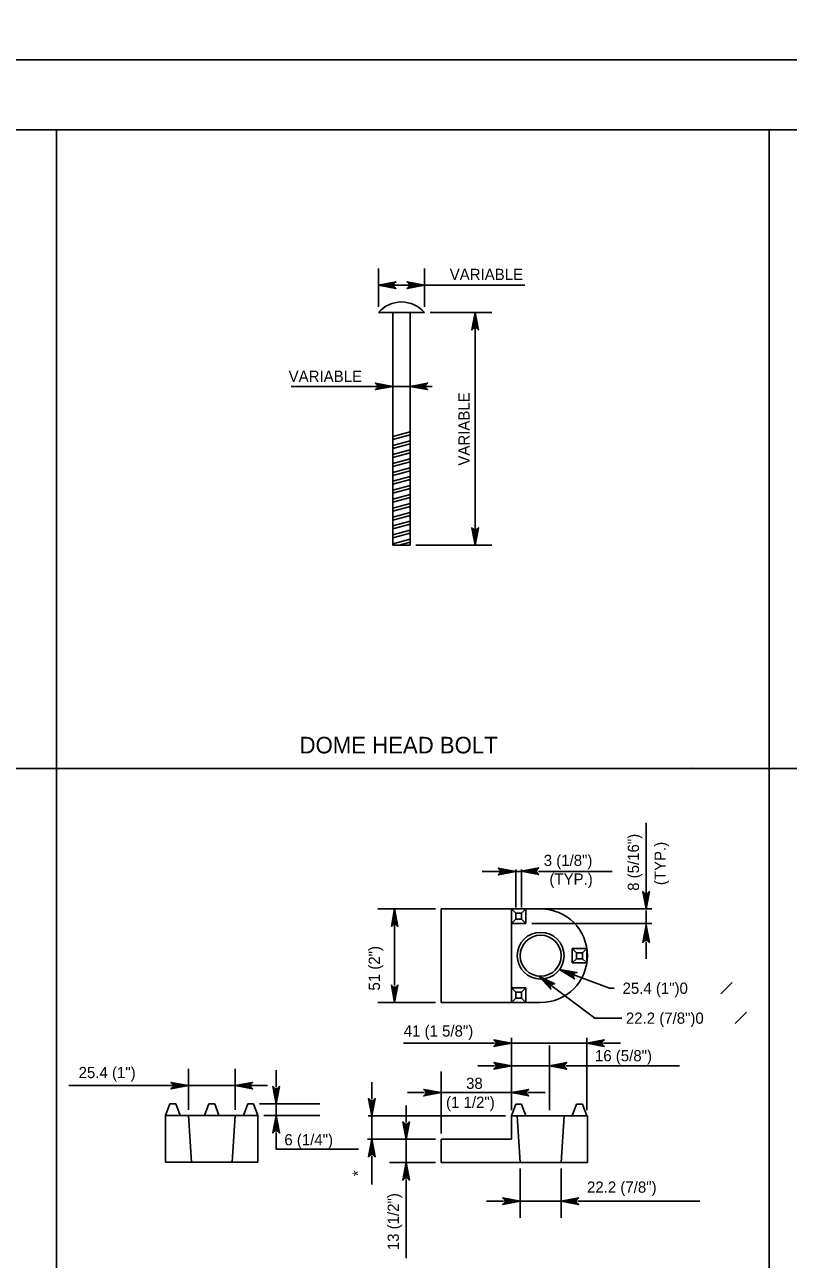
# Model space of a CAD drawing. Extents: x 0 to 36.3, y -66 to 0.
# Drawn here: x 9.04 to 17.21, y -56.84 to -43.62 of the extents above; entities that cross this region are included whole.
import ezdxf

# ---------------------------------------------------------------- set-up
doc = ezdxf.new("R2010")
doc.units = 0
for name, color, linetype in [('1', 7, 'Continuous'), ('3', 7, 'Continuous'), ('4', 7, 'Continuous'), ('5', 7, 'Continuous'), ('63', 7, 'Continuous')]:
    doc.layers.add(name, color=color, linetype=linetype)

msp = doc.modelspace()

# ---------------------------------------------------------------- linework, layer by layer
at = {"layer": '1'}
msp.add_lwpolyline([(1.75, -65.25), (33.25, -65.25), (33.25, -44.75), (1.75, -44.75)], close=True, dxfattribs=at)
at = {"layer": '3'}
for p, q in [((9.375, -65.25), (9.375, -44.75)), ((17, -65.25), (17, -44.75)), ((12.821, -46.643), (12.821, -46.234)), ((13.313, -46.643), (13.313, -46.234)), ((12.821, -46.412), (14.388, -46.412)), ((13.313, -46.412), (13.313, -46.412)), ((13.375, -46.705), (14.033, -46.705)), ((13.855, -49.193), (13.855, -46.705)), ((12.857, -47.495), (11.887, -47.495)), ((12.975, -47.451), (12.975, -47.672)), ((13.16, -47.495), (12.975, -47.495)), ((13.16, -47.451), (13.16, -47.672)), ((13.278, -47.495), (13.396, -47.495)), ((13.221, -49.193), (14.033, -49.193)), ((1.75, -51.583), (32.25, -51.583)), ((16.171, -51.569), (16.171, -51.569)), ((16.482, -53.994), (16.604, -53.872)), ((16.638, -54.312), (16.76, -54.19))]:
    msp.add_line(p, q, dxfattribs=at)
for points in [[(12.821, -46.412), (13.008, -46.377), (12.993, -46.387), (12.986, -46.399), (12.984, -46.412), (12.986, -46.424), (12.993, -46.437), (13.008, -46.447), (12.821, -46.412), (12.993, -46.437), (12.986, -46.424), (12.821, -46.412), (12.984, -46.412), (12.986, -46.399), (12.821, -46.412), (12.993, -46.387)], [(13.313, -46.412), (13.127, -46.447), (13.141, -46.437), (13.149, -46.424), (13.151, -46.412), (13.149, -46.399), (13.141, -46.387), (13.127, -46.377), (13.313, -46.412), (13.141, -46.387), (13.149, -46.399), (13.313, -46.412), (13.151, -46.412), (13.149, -46.424), (13.313, -46.412), (13.141, -46.437)], [(13.855, -46.705), (13.89, -46.891), (13.88, -46.877), (13.868, -46.869), (13.855, -46.867), (13.843, -46.869), (13.83, -46.877), (13.821, -46.891), (13.855, -46.705), (13.83, -46.877), (13.843, -46.869), (13.855, -46.705), (13.855, -46.867), (13.868, -46.869), (13.855, -46.705), (13.88, -46.877)], [(12.975, -47.495), (12.789, -47.53), (12.803, -47.52), (12.81, -47.508), (12.812, -47.495), (12.81, -47.483), (12.803, -47.47), (12.789, -47.46), (12.975, -47.495), (12.803, -47.47), (12.81, -47.483), (12.975, -47.495), (12.812, -47.495), (12.81, -47.508), (12.975, -47.495), (12.803, -47.52)], [(13.16, -47.495), (13.346, -47.46), (13.332, -47.47), (13.324, -47.483), (13.322, -47.495), (13.324, -47.508), (13.332, -47.52), (13.346, -47.53), (13.16, -47.495), (13.332, -47.52), (13.324, -47.508), (13.16, -47.495), (13.322, -47.495), (13.324, -47.483), (13.16, -47.495), (13.332, -47.47)], [(13.855, -49.193), (13.821, -49.007), (13.83, -49.021), (13.843, -49.028), (13.855, -49.03), (13.868, -49.028), (13.88, -49.021), (13.89, -49.007), (13.855, -49.193), (13.88, -49.021), (13.868, -49.028), (13.855, -49.193), (13.855, -49.03), (13.843, -49.028), (13.855, -49.193), (13.83, -49.021)]]:
    msp.add_lwpolyline(points, dxfattribs=at)
for points in [[(12.939, -46.431), (12.939, -46.392), (12.821, -46.412)], [(13.195, -46.431), (13.195, -46.392), (13.313, -46.412)], [(13.875, -46.823), (13.836, -46.823), (13.855, -46.705)], [(12.857, -47.475), (12.857, -47.515), (12.975, -47.495)], [(13.278, -47.475), (13.278, -47.515), (13.16, -47.495)], [(13.875, -49.075), (13.836, -49.075), (13.855, -49.193)]]:
    msp.add_lwpolyline(points, close=True, dxfattribs=at)
at = {"layer": '4'}
for p, q in [((12.821, -46.705), (12.821, -46.705)), ((12.821, -46.705), (13.313, -46.705)), ((12.975, -46.705), (12.975, -47.972)), ((13.16, -46.705), (13.16, -47.972)), ((13.313, -46.705), (13.313, -46.705)), ((12.975, -47.972), (12.975, -49.193)), ((13.16, -47.972), (13.16, -49.193)), ((12.975, -49.193), (13.16, -49.193)), ((13.16, -49.193), (13.16, -49.193)), ((15.684, -52.923), (15.684, -52.165)), ((14.352, -52.687), (13.929, -52.687)), ((14.289, -53.071), (14.289, -52.663)), ((14.352, -53.071), (14.352, -52.663)), ((14.532, -52.687), (15.32, -52.687)), ((13.43, -53.087), (12.814, -53.087)), ((12.994, -53.907), (12.994, -53.087)), ((13.493, -53.087), (13.493, -54.087)), ((13.493, -53.087), (14.556, -53.087)), ((14.243, -53.087), (14.243, -54.087)), ((14.243, -53.087), (14.289, -53.133)), ((14.398, -53.087), (14.352, -53.133)), ((14.398, -53.087), (14.398, -53.243)), ((14.461, -53.087), (15.746, -53.087)), ((15.684, -53.259), (15.684, -53.103)), ((14.289, -53.197), (14.243, -53.243)), ((14.289, -53.133), (14.289, -53.197)), ((14.289, -53.133), (14.352, -53.133)), ((14.289, -53.197), (14.352, -53.197)), ((14.352, -53.133), (14.352, -53.197)), ((14.352, -53.197), (14.398, -53.243)), ((14.243, -53.243), (14.398, -53.243)), ((14.461, -53.243), (15.746, -53.243)), ((15.684, -53.439), (15.684, -53.619)), ((14.894, -53.509), (14.941, -53.556)), ((15.05, -53.509), (14.894, -53.509)), ((14.894, -53.509), (14.894, -53.665)), ((14.941, -53.619), (14.894, -53.665)), ((14.941, -53.556), (14.941, -53.619)), ((14.941, -53.556), (15.004, -53.556)), ((14.941, -53.619), (15.004, -53.619)), ((15.05, -53.509), (15.004, -53.556)), ((15.004, -53.556), (15.004, -53.619)), ((15.004, -53.619), (15.05, -53.665)), ((15.05, -53.509), (15.05, -53.665)), ((14.894, -53.665), (15.05, -53.665)), ((14.398, -53.932), (14.243, -53.932)), ((14.243, -53.932), (14.289, -53.978)), ((14.289, -53.978), (14.289, -54.041)), ((14.289, -53.978), (14.352, -53.978)), ((14.398, -53.932), (14.352, -53.978)), ((14.352, -53.978), (14.352, -54.041)), ((14.398, -53.932), (14.398, -54.087)), ((13.43, -54.087), (12.814, -54.087)), ((13.493, -54.087), (14.556, -54.087)), ((14.289, -54.041), (14.243, -54.087)), ((14.243, -54.087), (14.398, -54.087)), ((14.289, -54.041), (14.352, -54.041)), ((14.352, -54.041), (14.398, -54.087)), ((15.135, -54.255), (15.424, -54.255)), ((14.063, -54.523), (13.089, -54.523)), ((14.243, -55.239), (14.243, -54.465)), ((14.243, -54.523), (15.05, -54.523)), ((14.243, -55.239), (14.243, -54.549)), ((14.649, -55.239), (14.649, -54.549)), ((15.05, -55.239), (15.05, -54.465)), ((15.23, -54.523), (15.41, -54.523)), ((10.787, -55.235), (10.787, -54.797)), ((11.287, -55.235), (11.287, -54.797)), ((11.727, -54.991), (11.727, -54.811)), ((14.063, -54.766), (13.883, -54.766)), ((14.243, -54.766), (14.649, -54.766)), ((14.243, -55.239), (14.243, -54.784)), ((14.829, -54.766), (16.041, -54.766)), ((12.751, -55.121), (12.751, -54.941)), ((13.493, -55.489), (13.493, -54.825)), ((9.508, -54.977), (10.622, -54.977)), ((10.787, -54.977), (11.287, -54.977)), ((11.633, -54.977), (11.453, -54.977)), ((13.313, -55.052), (13.133, -55.052)), ((13.493, -55.052), (14.243, -55.052)), ((14.423, -55.052), (14.603, -55.052)), ((10.59, -55.171), (10.543, -55.297)), ((10.653, -55.171), (10.59, -55.171)), ((10.653, -55.171), (10.699, -55.297)), ((11.006, -55.171), (10.961, -55.297)), ((11.069, -55.171), (11.006, -55.171)), ((11.069, -55.171), (11.114, -55.297)), ((11.422, -55.171), (11.376, -55.297)), ((11.485, -55.171), (11.422, -55.171)), ((11.485, -55.171), (11.531, -55.297)), ((11.548, -55.171), (12.194, -55.171)), ((11.727, -55.171), (11.727, -55.297)), ((13.118, -55.371), (13.118, -55.191)), ((14.243, -55.301), (14.289, -55.176)), ((14.289, -55.176), (14.352, -55.176)), ((14.352, -55.176), (14.398, -55.301)), ((14.894, -55.301), (14.941, -55.176)), ((14.941, -55.176), (15.004, -55.176)), ((15.004, -55.176), (15.05, -55.301)), ((11.531, -55.297), (10.543, -55.297)), ((10.543, -55.297), (10.543, -55.797)), ((10.787, -55.297), (10.819, -55.797)), ((11.287, -55.297), (11.256, -55.797)), ((11.531, -55.297), (11.531, -55.797)), ((11.594, -55.297), (12.194, -55.297)), ((14.18, -55.301), (12.712, -55.301)), ((12.751, -55.301), (12.751, -55.551)), ((14.243, -55.301), (15.056, -55.301)), ((14.243, -55.301), (14.243, -55.551)), ((14.337, -55.801), (14.306, -55.301)), ((14.774, -55.801), (14.806, -55.301)), ((15.056, -55.301), (15.056, -55.801)), ((11.727, -55.477), (11.727, -55.657)), ((13.43, -55.551), (12.703, -55.551)), ((13.43, -55.551), (12.938, -55.551)), ((13.118, -55.551), (13.118, -55.801)), ((13.493, -55.551), (14.243, -55.551)), ((13.493, -55.551), (13.493, -55.801)), ((11.727, -55.657), (12.608, -55.657)), ((12.751, -55.731), (12.751, -56.035)), ((11.531, -55.797), (10.543, -55.797)), ((13.43, -55.801), (12.938, -55.801)), ((13.43, -55.801), (13.25, -55.801)), ((13.493, -55.801), (15.056, -55.801)), ((14.337, -55.864), (14.337, -56.393)), ((14.774, -55.864), (14.774, -56.393)), ((13.118, -55.981), (13.118, -56.825)), ((14.157, -56.213), (13.977, -56.213)), ((14.337, -56.213), (14.774, -56.213)), ((14.954, -56.213), (16.259, -56.213))]:
    msp.add_line(p, q, dxfattribs=at)
for points in [[(14.289, -52.687), (14.102, -52.722), (14.117, -52.712), (14.124, -52.7), (14.126, -52.687), (14.124, -52.675), (14.117, -52.662), (14.102, -52.652), (14.289, -52.687), (14.117, -52.662), (14.124, -52.675), (14.289, -52.687), (14.126, -52.687), (14.124, -52.7), (14.289, -52.687), (14.117, -52.712)], [(14.349, -52.683), (14.536, -52.648), (14.521, -52.658), (14.514, -52.67), (14.512, -52.683), (14.514, -52.695), (14.521, -52.708), (14.536, -52.718), (14.349, -52.683), (14.521, -52.708), (14.514, -52.695), (14.349, -52.683), (14.512, -52.683), (14.514, -52.67), (14.349, -52.683), (14.521, -52.658)], [(15.684, -53.087), (15.649, -52.901), (15.659, -52.915), (15.672, -52.923), (15.684, -52.925), (15.697, -52.923), (15.709, -52.915), (15.719, -52.901), (15.684, -53.087), (15.709, -52.915), (15.697, -52.923), (15.684, -53.087), (15.684, -52.925), (15.672, -52.923), (15.684, -53.087), (15.659, -52.915)], [(12.994, -53.087), (13.029, -53.274), (13.019, -53.259), (13.006, -53.252), (12.994, -53.25), (12.981, -53.252), (12.969, -53.259), (12.959, -53.274), (12.994, -53.087), (12.969, -53.259), (12.981, -53.252), (12.994, -53.087), (12.994, -53.25), (13.006, -53.252), (12.994, -53.087), (13.019, -53.259)], [(15.684, -53.259), (15.719, -53.445), (15.709, -53.431), (15.697, -53.423), (15.684, -53.421), (15.672, -53.423), (15.659, -53.431), (15.649, -53.445), (15.684, -53.259), (15.659, -53.431), (15.672, -53.423), (15.684, -53.259), (15.684, -53.421), (15.697, -53.423), (15.684, -53.259), (15.709, -53.431)], [(14.757, -53.735), (15.291, -53.935), (15.342, -53.935)], [(14.757, -53.735), (14.944, -53.768), (14.927, -53.772), (14.916, -53.782), (14.909, -53.792), (14.907, -53.805), (14.909, -53.819), (14.919, -53.834), (14.757, -53.735), (14.909, -53.819), (14.907, -53.805), (14.757, -53.735), (14.909, -53.792), (14.916, -53.782), (14.757, -53.735), (14.927, -53.772)], [(14.537, -53.805), (15.135, -54.255)], [(14.537, -53.805), (14.707, -53.889), (14.689, -53.888), (14.676, -53.894), (14.666, -53.903), (14.661, -53.914), (14.659, -53.928), (14.665, -53.945), (14.537, -53.805), (14.659, -53.928), (14.661, -53.914), (14.537, -53.805), (14.666, -53.903), (14.676, -53.894), (14.537, -53.805), (14.689, -53.888)], [(12.994, -54.087), (12.959, -53.901), (12.969, -53.915), (12.981, -53.923), (12.994, -53.925), (13.006, -53.923), (13.019, -53.915), (13.029, -53.901), (12.994, -54.087), (13.019, -53.915), (13.006, -53.923), (12.994, -54.087), (12.994, -53.925), (12.981, -53.923), (12.994, -54.087), (12.969, -53.915)], [(14.243, -54.523), (14.056, -54.557), (14.071, -54.548), (14.078, -54.535), (14.08, -54.523), (14.078, -54.51), (14.071, -54.498), (14.056, -54.488), (14.243, -54.523), (14.071, -54.498), (14.078, -54.51), (14.243, -54.523), (14.08, -54.523), (14.078, -54.535), (14.243, -54.523), (14.071, -54.548)], [(15.05, -54.523), (15.236, -54.488), (15.222, -54.498), (15.214, -54.51), (15.212, -54.523), (15.214, -54.535), (15.222, -54.548), (15.236, -54.557), (15.05, -54.523), (15.222, -54.548), (15.214, -54.535), (15.05, -54.523), (15.212, -54.523), (15.214, -54.51), (15.05, -54.523), (15.222, -54.498)], [(14.243, -54.766), (14.056, -54.801), (14.071, -54.791), (14.078, -54.778), (14.08, -54.766), (14.078, -54.753), (14.071, -54.741), (14.056, -54.731), (14.243, -54.766), (14.071, -54.741), (14.078, -54.753), (14.243, -54.766), (14.08, -54.766), (14.078, -54.778), (14.243, -54.766), (14.071, -54.791)], [(14.649, -54.766), (14.836, -54.731), (14.821, -54.741), (14.814, -54.753), (14.812, -54.766), (14.814, -54.778), (14.821, -54.791), (14.836, -54.801), (14.649, -54.766), (14.821, -54.791), (14.814, -54.778), (14.649, -54.766), (14.812, -54.766), (14.814, -54.753), (14.649, -54.766), (14.821, -54.741)], [(10.787, -54.977), (10.601, -55.012), (10.615, -55.002), (10.623, -54.99), (10.625, -54.977), (10.623, -54.965), (10.615, -54.952), (10.601, -54.942), (10.787, -54.977), (10.615, -54.952), (10.623, -54.965), (10.787, -54.977), (10.625, -54.977), (10.623, -54.99), (10.787, -54.977), (10.615, -55.002)], [(11.287, -54.977), (11.474, -54.942), (11.46, -54.952), (11.452, -54.965), (11.45, -54.977), (11.452, -54.99), (11.46, -55.002), (11.474, -55.012), (11.287, -54.977), (11.46, -55.002), (11.452, -54.99), (11.287, -54.977), (11.45, -54.977), (11.452, -54.965), (11.287, -54.977), (11.46, -54.952)], [(11.727, -55.171), (11.692, -54.985), (11.702, -54.999), (11.715, -55.007), (11.727, -55.009), (11.74, -55.007), (11.752, -54.999), (11.762, -54.985), (11.727, -55.171), (11.752, -54.999), (11.74, -55.007), (11.727, -55.171), (11.727, -55.009), (11.715, -55.007), (11.727, -55.171), (11.702, -54.999)], [(13.493, -55.052), (13.306, -55.087), (13.321, -55.077), (13.328, -55.064), (13.33, -55.052), (13.328, -55.039), (13.321, -55.027), (13.306, -55.017), (13.493, -55.052), (13.321, -55.027), (13.328, -55.039), (13.493, -55.052), (13.33, -55.052), (13.328, -55.064), (13.493, -55.052), (13.321, -55.077)], [(14.243, -55.052), (14.429, -55.017), (14.415, -55.027), (14.407, -55.039), (14.405, -55.052), (14.407, -55.064), (14.415, -55.077), (14.429, -55.087), (14.243, -55.052), (14.415, -55.077), (14.407, -55.064), (14.243, -55.052), (14.405, -55.052), (14.407, -55.039), (14.243, -55.052), (14.415, -55.027)], [(12.751, -55.301), (12.716, -55.115), (12.726, -55.129), (12.739, -55.137), (12.751, -55.139), (12.764, -55.137), (12.776, -55.129), (12.786, -55.115), (12.751, -55.301), (12.776, -55.129), (12.764, -55.137), (12.751, -55.301), (12.751, -55.139), (12.739, -55.137), (12.751, -55.301), (12.726, -55.129)], [(11.727, -55.297), (11.762, -55.484), (11.752, -55.469), (11.74, -55.462), (11.727, -55.46), (11.715, -55.462), (11.702, -55.469), (11.692, -55.484), (11.727, -55.297), (11.702, -55.469), (11.715, -55.462), (11.727, -55.297), (11.727, -55.46), (11.74, -55.462), (11.727, -55.297), (11.752, -55.469)], [(13.118, -55.551), (13.083, -55.365), (13.093, -55.379), (13.106, -55.387), (13.118, -55.389), (13.131, -55.387), (13.143, -55.379), (13.153, -55.365), (13.118, -55.551), (13.143, -55.379), (13.131, -55.387), (13.118, -55.551), (13.118, -55.389), (13.106, -55.387), (13.118, -55.551), (13.093, -55.379)], [(12.751, -55.551), (12.786, -55.738), (12.776, -55.724), (12.764, -55.716), (12.751, -55.714), (12.739, -55.716), (12.726, -55.724), (12.716, -55.738), (12.751, -55.551), (12.726, -55.724), (12.739, -55.716), (12.751, -55.551), (12.751, -55.714), (12.764, -55.716), (12.751, -55.551), (12.776, -55.724)], [(13.118, -55.801), (13.153, -55.988), (13.143, -55.974), (13.131, -55.966), (13.118, -55.964), (13.106, -55.966), (13.093, -55.974), (13.083, -55.988), (13.118, -55.801), (13.093, -55.974), (13.106, -55.966), (13.118, -55.801), (13.118, -55.964), (13.131, -55.966), (13.118, -55.801), (13.143, -55.974)], [(14.337, -56.213), (14.151, -56.248), (14.165, -56.238), (14.172, -56.226), (14.175, -56.213), (14.172, -56.201), (14.165, -56.188), (14.151, -56.178), (14.337, -56.213), (14.165, -56.188), (14.172, -56.201), (14.337, -56.213), (14.175, -56.213), (14.172, -56.226), (14.337, -56.213), (14.165, -56.238)], [(14.774, -56.213), (14.961, -56.178), (14.946, -56.188), (14.939, -56.201), (14.937, -56.213), (14.939, -56.226), (14.946, -56.238), (14.961, -56.248), (14.774, -56.213), (14.946, -56.238), (14.939, -56.226), (14.774, -56.213), (14.937, -56.213), (14.939, -56.201), (14.774, -56.213), (14.946, -56.188)]]:
    msp.add_lwpolyline(points, dxfattribs=at)
for radius in [0.25, 0.219]:
    msp.add_circle((14.556, -53.587), radius, dxfattribs=at)
for centre, radius, start, end in [((13.067, -46.917), 0.325, 40.7962, 139.2038), ((14.556, -53.587), 0.5, 270, 90)]:
    msp.add_arc(centre, radius, start, end, dxfattribs=at)
at = {"layer": '5'}
for p, q in [((12.975, -48.033), (13.16, -47.983)), ((12.975, -48.065), (13.16, -48.015)), ((12.975, -48.128), (13.16, -48.079)), ((12.975, -48.16), (13.16, -48.111)), ((12.975, -48.224), (13.16, -48.175)), ((12.975, -48.256), (13.16, -48.206)), ((12.975, -48.32), (13.16, -48.27)), ((12.975, -48.351), (13.16, -48.302)), ((12.975, -48.415), (13.16, -48.366)), ((12.975, -48.447), (13.16, -48.398)), ((12.975, -48.511), (13.16, -48.461)), ((12.975, -48.542), (13.16, -48.493)), ((12.975, -48.606), (13.16, -48.557)), ((12.975, -48.638), (13.16, -48.589)), ((12.975, -48.702), (13.16, -48.652)), ((12.975, -48.733), (13.16, -48.684)), ((12.975, -48.797), (13.16, -48.748)), ((12.975, -48.829), (13.16, -48.78)), ((12.975, -48.893), (13.16, -48.843)), ((12.975, -48.925), (13.16, -48.875)), ((12.975, -48.988), (13.16, -48.939)), ((12.975, -49.02), (13.16, -48.971)), ((12.975, -49.084), (13.16, -49.034)), ((12.975, -49.116), (13.16, -49.066)), ((12.975, -49.179), (13.16, -49.13)), ((13.043, -49.193), (13.16, -49.162))]:
    msp.add_line(p, q, dxfattribs=at)
at = {"layer": '63'}
for points in [[(0, -44), (34, -44), (34, -22), (0, -22)], [(0, -66), (34, -66), (34, -44), (0, -44)]]:
    msp.add_lwpolyline(points, close=True, dxfattribs=at)

# ---------------------------------------------------------------- texts
at = {"layer": '3'}
for s, height, p in [('VARIABLE', 0.12, (13.583, -46.357)), ('VARIABLE', 0.12, (11.86, -47.447)), ('DOME HEAD BOLT', 0.17717, (11.977, -51.422))]:
    msp.add_text(s, height=height, dxfattribs=at).set_placement(p)
for s, p in [('VARIABLE', (13.796, -48.343)), ('51 (2")', (12.836, -53.96))]:
    msp.add_text(s, height=0.12, rotation=90, dxfattribs=at).set_placement(p)
at = {"layer": '4'}
for s, p in [('8 (5/16")', (15.608, -52.893)), ('(TYP.)', (15.894, -52.832)), ('*', (12.662, -55.947)), ('13 (1/2")', (13.039, -56.738))]:
    msp.add_text(s, height=0.12, rotation=90, dxfattribs=at).set_placement(p)
for s, p in [('3 (1/8")', (14.589, -52.627)), ('(TYP.)', (14.65, -52.826)), ('25.4 (1")0', (15.432, -53.995)), ('22.2 (7/8")0', (15.468, -54.315)), ('41 (1 5/8")', (13.091, -54.452)), ('16 (5/8")', (15.137, -54.717)), ('25.4 (1")', (9.613, -54.897)), ('38', (13.758, -55.012)), ('(1 1/2")', (13.544, -55.215)), ('6 (1/4")', (11.814, -55.616)), ('22.2 (7/8")', (15.052, -56.123))]:
    msp.add_text(s, height=0.12, dxfattribs=at).set_placement(p)

doc.saveas('drawing.dxf')
